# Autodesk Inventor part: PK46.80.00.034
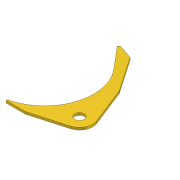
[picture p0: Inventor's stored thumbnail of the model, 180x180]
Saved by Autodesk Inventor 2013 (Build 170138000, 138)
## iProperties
Shininess: 64.0
Length Units: 11269
Angle Units: 11279
Time Units: 11290
Mass Units: 11283
Length Display Precision: 3
Angle Display Precision: 2
Compacted: True
Part Number: PK46.80.00.034
Document SubType Name: Modeling
Created: 2005-01
Material: Steel, Mild
Designer: SAlex
Manufacturer: Standard
Standards Organization: Custom
Density: 7.86 g/cm^3
Mass: 20870.5 g
Surface Area: 3215.19 cm^2
Volume: 2655.27 cm^3
Density: 0.0
Volumn: 0.0
Area: 0.0
PropertySet Name: Model Information
Control State: 0
Master: False
Checked Out: False
Checked Out Date: 2008-10-15
Last Check In Date: 2008-10-15
Author: SAlex
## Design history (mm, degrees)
sketch "Sketch1"
  geometry: L1 (-420, -188)-(-260, -188); L2 (-260, -188)-(29.987, -105.834); L3 (-20, 350)-(102.306, 40.417); L4 (-20, 350)-(-215, 635); L5 (-215, 635)-(-333.188, 675.134); L6 (-333.188, 675.134)-(-348.509, 662.278); L7 (-348.509, 662.278)-(-197.454, 482.257); L8 (-420, -177.95)-(-420, -188); L9 (-510, 220)-(-197.454, 482.257); C1 r 40 at (0, 0); A1 r 110 centre (0, 0) between (29.987, -105.834) and (102.306, 40.417); A2 r 408 centre (-510, 220) between (-420, -177.95) and (-197.454, 482.257)
  constraints: 18 end point, 4 point on circle, 3 centre point, 3 tangent, 2 perpendicular, 1 coincident, 1 horizontal, 1 other
  dimensions: "d0" = 80 diameter of C1; "d1" = 110 radius of A1; "d3" = 188 distance from line of L1 A1.centre; "d25" = 510 horizontal distance of L9.start C1.centre; "d26" = 220 vertical distance of L9.start C1.centre; "d28" = 408 radius of A2; "d29" = 90 distance from line of L8 L9.start; "d30" = 160 distance of L1.start L1.end; "d31" = 235 distance of L6.end L7.end; "d32" = 130 vertical distance of L3.start L9.start; "d33" = 490 horizontal distance of L3.start L9.start; "d34" = 295 horizontal distance of L4.end L9.start; "d35" = 130 deg angle of L8 L9; "d36" = 20 distance of L5.end L6.end; "d37" = 415 vertical distance of L4.end L9.start
extrude "Extrusion1" new body sketch "Sketch1" distance "d10" = 20; taper "d11" = 0 deg
body "Solid1"
